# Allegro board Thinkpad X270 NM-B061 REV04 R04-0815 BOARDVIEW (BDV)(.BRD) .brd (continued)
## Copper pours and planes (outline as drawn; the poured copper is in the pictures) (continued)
N50768281 on BOTTOM (solid shape): 71.96,108.67 71.96,105.92 71.69,105.65 69.73,105.65 69.68,105.6 69.68,105.04 69.78,104.94 72.02,104.94 72.22,104.74 72.22,102.78 71.2,101.76 68.16,101.76 68.04,101.64 67.45,101.64 67.32,101.76 67.32,102.57 65.66,104.23 65.66,106.88 65.68,106.9 66.51,106.9 66.77,107.17 66.77,107.77 67.83,108.82 71.81,108.82
N50768289 on BOTTOM: 60.18,107.28 59.7,107.28 59.6,107.38 59.6,109.72 59.6,109.76 59.7,109.85 59.85,109.85 60.23,109.47 60.23,107.33
N50768292 on BOTTOM (solid shape): 60.36,111.48 60.36,110.31 61.32,109.35 61.32,108.78 61.6,108.51 62.46,108.51 62.53,108.44 62.53,108.28 62.45,108.2 60.61,108.2 60.51,108.3 60.51,109.5 59.77,110.23 59.77,111.51 59.93,111.67 60.17,111.67
N50768448 on BOTTOM (solid shape): 62.59,108.01 62.59,107.85 62.57,107.83 62.51,107.83 62.45,107.83 62.04,107.83 61.99,107.83 61.93,107.81 61.87,107.81 61.87,107.81 61.81,107.81 61.74,107.75 61.74,107.43 61.88,107.3 61.93,107.3 61.99,107.28 62.04,107.27 62.45,107.27 62.55,107.17 62.55,107.1 62.48,107.03 61.42,107.03 61.17,107.28 60.59,107.28 60.54,107.33 60.54,107.95 60.7,108.11 62.49,108.11
N50768459 on BOTTOM (solid shape): 66.35,108.39 66.35,107.1 66.28,107.02 65.67,107.02 65.62,107.07 65.62,108.42 65.64,108.44 66.3,108.44
N50768485 on BOTTOM: 64.93,109.22 64.93,109.91 65.35,110.33 65.35,110.82 65.47,110.93 66.1,110.93 66.1,110.93 66.4,111.24 66.4,111.51 67.01,111.51 67.01,110.74 66.57,110.29 66.36,110.29 65.24,109.17 64.98,109.17
N50768505 on BOTTOM: 65.16,102.45 65.77,102.45 65.92,102.6 66.68,102.6 66.74,102.55 66.74,101.71 66.69,101.67 65.24,101.67 65.11,101.8 65.11,102.4
N51231994 on TOP: 278.86,120.76 278.84,120.74 278.84,118.23 278.39,117.77 276.3,117.77 276.12,117.95 276.12,120.84 275.64,121.33 275.64,122.67 276.73,123.77 276.73,131.74 277.2,132.21 278.63,132.21 278.86,131.98
N51231994 on GND1, GND3: 276.34,117.67 276.12,117.89 276.12,131.32 279.01,134.26 283.91,134.26 285.28,135.63 288.18,135.63 288.33,135.47 288.32,135.4 288.32,135.32 288.32,120.84 288.33,120.68 288.37,120.53 285.51,117.67

Small or netless copper shapes (teardrops, artwork), in the pictures only: 5 on TOP, 13 on BOTTOM

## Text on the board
Ref Des/Silkscreen Bottom: 1 | M2X2.7 | M2X4
User.Comments: CR_22MED_1 | CR_44ED_1
User.40: FIGURE | SIZE | 8.0 | 10.0 | 16.0 | 22.0 | 28.0 | 35.0 | 39.0 | 43.0 | 67.0 | 75.0 | 98.0 | 110.0 | 134.0 | 138.0 | 264.0 | 24.0 | 26.0 | 31.0 | 47.0 | 63.0 | 35.0x16.0 | 39.0x20.0 | 43.0x20.0 | 47.0x20.0 | 59.0x20.0 | 59.0x31.0 | 67.0x39.0 | 77.0x31.0 | 79.0x31.0 | 94.0x24.0 | 94.0x39.0 | 102.0x31.0 | 102.0x71.0 | 110.0x31.0 | 157.0x31.0 | 31.0x26.0 | 43.0x31.0 | 51.0x43.0 | 63.0x47.0 | DRILL CHART: TOP to BOTTOM | ALL UNITS ARE IN MILS | PLATED | NON-PLATED | QTY | 4084 | 943 | 10 | 19 | 18 | 8 | 4 | 7 | 1 | 3 | 2 | 6
